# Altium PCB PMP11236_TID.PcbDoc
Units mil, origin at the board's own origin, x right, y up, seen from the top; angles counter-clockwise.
Board outline 1771.65 x 787.4 mil, 2 copper layers (Top Layer, Bottom Layer), stack 62 mil thick; 37 components, 20 nets, 78 pads, 8 vias.
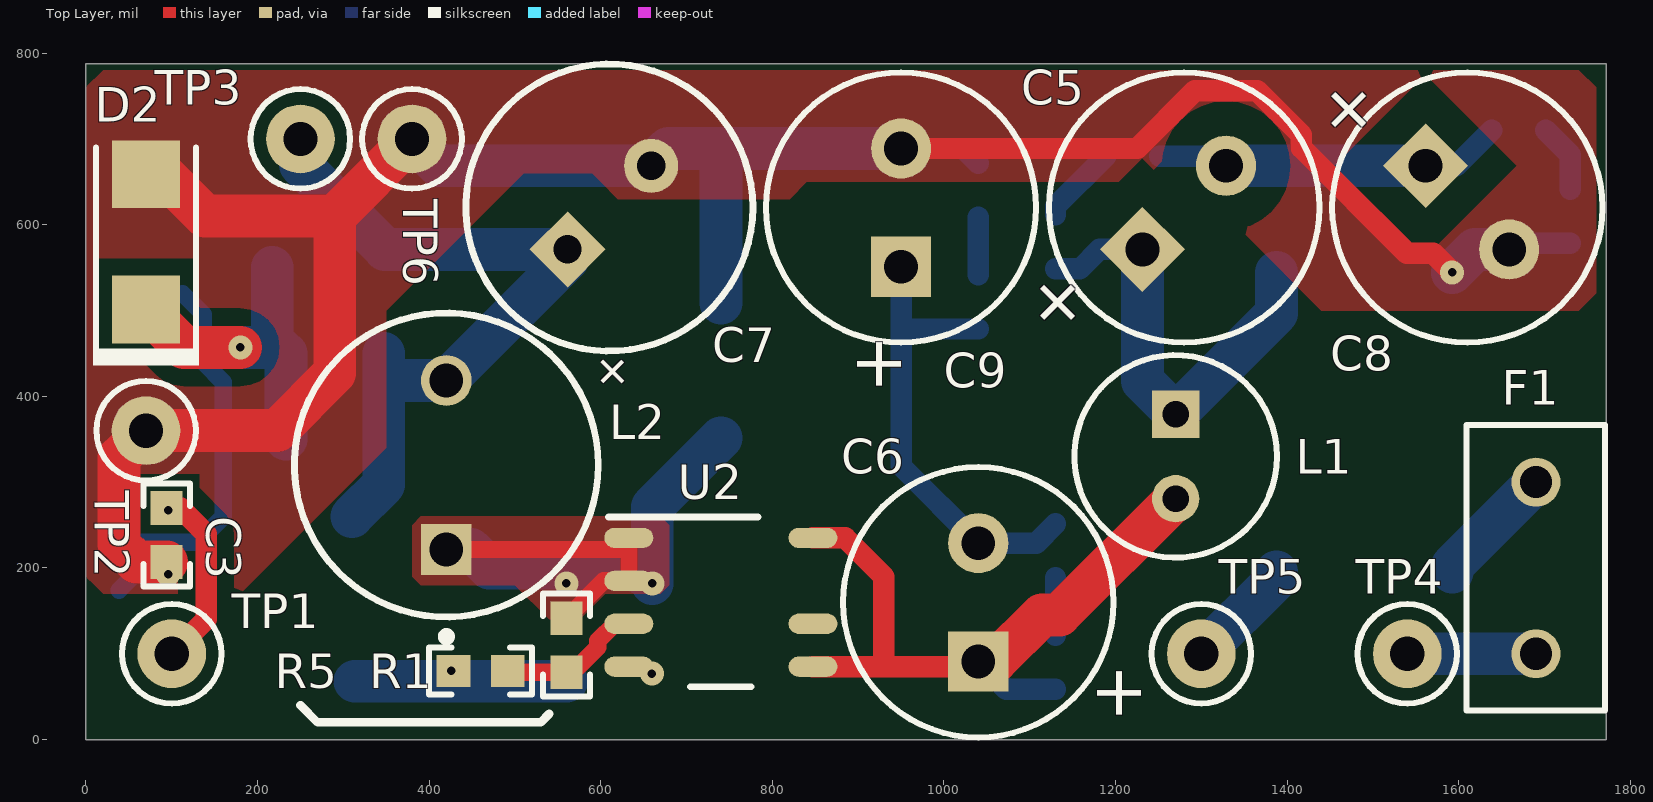
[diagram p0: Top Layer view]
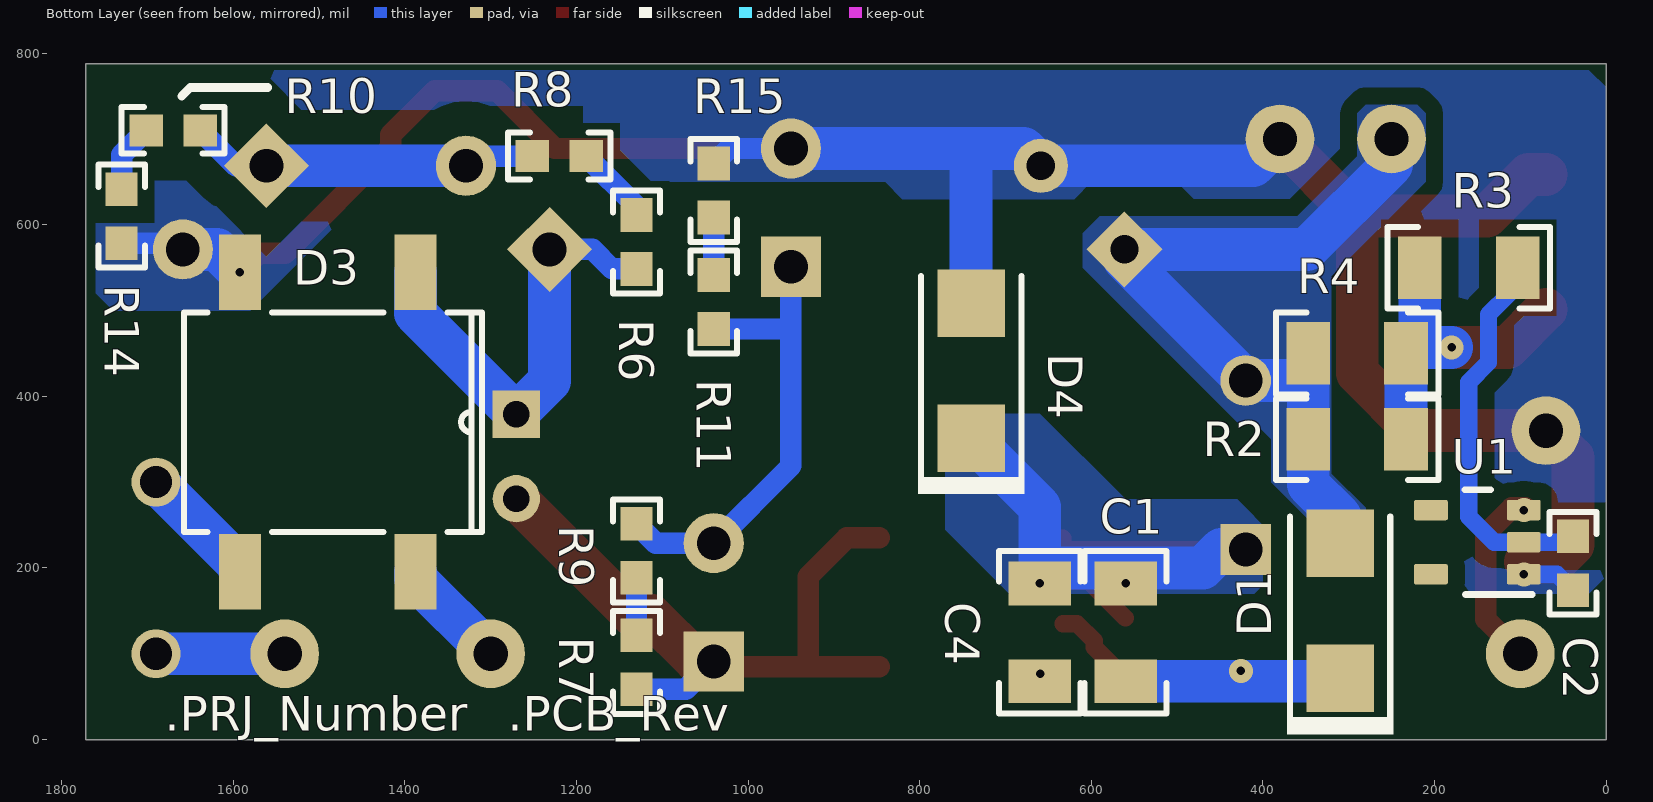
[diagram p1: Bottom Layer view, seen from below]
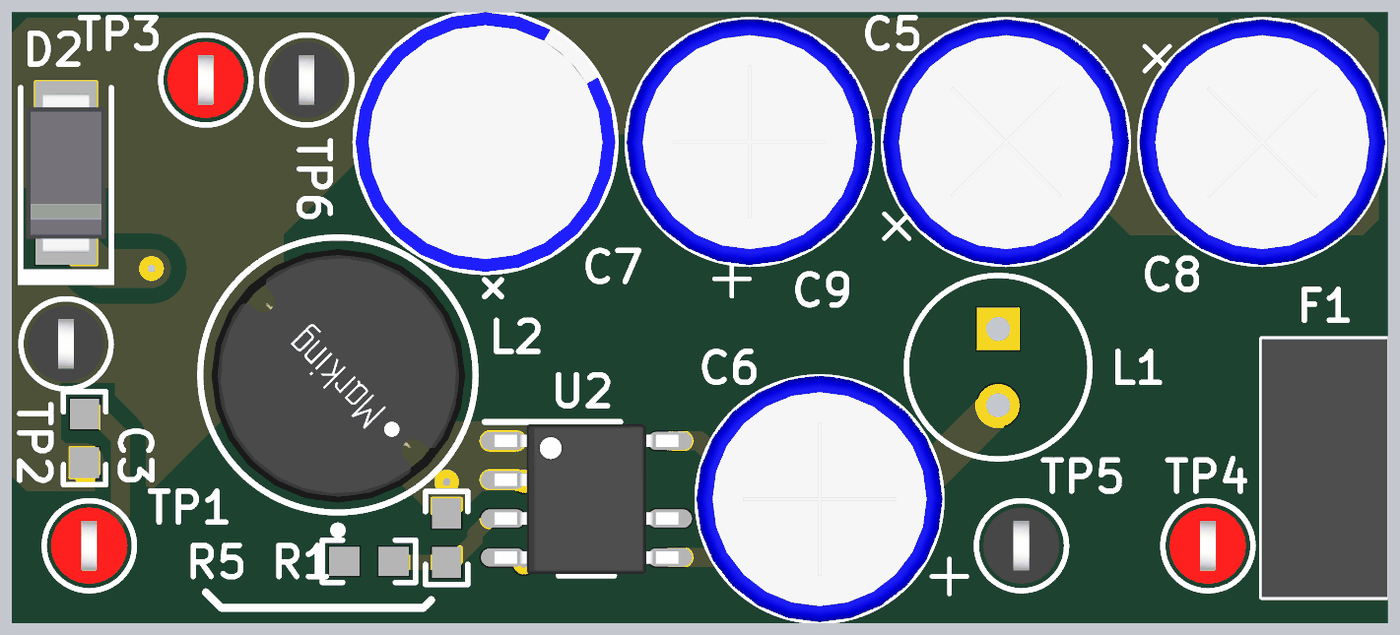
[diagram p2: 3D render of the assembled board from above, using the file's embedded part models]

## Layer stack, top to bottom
Top Solder: solder mask 0.4, Solder Resist, Dk 3.5
Top Layer: signal copper 1.4
Dielectric1: core 59.2, FR-4, Dk 4.8
Bottom Layer: signal copper 1.4
Bottom Solder: solder mask 0.4, Solder Resist, Dk 3.5

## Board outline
0,0 1771.65,0 1771.65,787.4 0,787.4

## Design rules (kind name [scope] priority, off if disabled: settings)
AcuteAngle [All] p1: minimum=4.50000000000000E+0001 checktracksonly=FALSE
AssemblyTestPointUsage [All] p1: valid=2
Clearance Clearance_1 [InNetClass('HV') vs InNet('GND')] p1: gap=40
Clearance Clearance_Keepouts [((IsTrack Or IsArc) And Not InPoly) And IsFree and IsKeepOut vs ((IsTrack Or IsArc) And Not InPoly) And IsFree and IsKeepOut] p2: gap=0
Clearance Clearance_BoardEdge_MountingHoles [OnCopper and InComponentClass('Mounting Holes') vs IsKeepOut] p3: gap=40
Clearance Clearance_BoardEdge_Poly [OnCopper and InPoly vs IsKeepOut] p4: gap=25
Clearance Clearance_BoardEdge [OnCopper and Not InComponentClass('Logo') and not InComponentClass('FiducialMark') and not InRegion(1000,500,4000,800) and Not IsKeepout vs IsKeepOut] p5: gap=75
Clearance Clearance_Poly [InPolygon] p6: gap=20
Clearance [All] p7: gap=7.87
ComponentClearance ComponentClearance_MountingHoles_FiducialMarks [InComponentClass('Mounting Holes') vs InComponentClass('FiducialMark')] p1: gap=20 collisioncheckmode=3 verticalgap=10 showdistances=FALSE
ComponentClearance ComponentClearance_Shunt [InComponentClass('Header') vs InComponentClass('Shunt')] p2: gap=0 collisioncheckmode=3 verticalgap=0 showdistances=FALSE
ComponentClearance ComponentClearance_Logo [InComponentClass('Logo')] p3: gap=5 collisioncheckmode=3 verticalgap=10 showdistances=FALSE
ComponentClearance ComponentClearance_ScrewToNut [(HasFootprint('NY PMS 440 0025 PH')) vs (HasFootprint('Keystone_1902C'))] p4: gap=20 collisioncheckmode=3 verticalgap=100000 showdistances=FALSE
ComponentClearance ComponentClearance_MountingHoles [InComponentClass('Mounting Holes')] p5: gap=20 collisioncheckmode=3 verticalgap=10 showdistances=FALSE
ComponentClearance ComponentClearance_SmallPassives [HasFootprint('0201*') or HasFootprint('0402*') or HasFootprint('0508') or HasFootprint('0603*') or HasFootprint('0612') or HasFootprint('0805*') or HasFootprint('0815*') or HasFootprint('0830*') or HasFootprint('1206*') or HasFootprint('1210*') or HasFootprint('1808*') or HasFootprint('1812*') or HasFootprint('1825*') or HasFootprint('2010*') or HasFootprint('2220*') or HasFootprint('2225*') or HasFootprint('2512*') or HasFootprint('2728*') or HasFootprint('3518*') vs HasFootprint('0201*') or HasFootprint('0402*') or HasFootprint('0508') or HasFootprint('0603*') or HasFootprint('0612') or HasFootprint('0805*') or HasFootprint('0815*') or HasFootprint('0830*') or HasFootprint('1206*') or HasFootprint('1210*') or HasFootprint('1808*') or HasFootprint('1812*') or HasFootprint('1825*') or HasFootprint('2010*') or HasFootprint('2220*') or HasFootprint('2225*') or HasFootprint('2512*') or HasFootprint('2728*') or HasFootprint('3518*')] p6: gap=20 collisioncheckmode=3 verticalgap=20 showdistances=FALSE
ComponentClearance ComponentClearance_THtoSMT [IsThruComponent vs IsSMTComponent] p7: gap=10 collisioncheckmode=3 verticalgap=10 showdistances=FALSE
ComponentClearance ComponentClearance_THtoTH [IsThruComponent vs IsThruComponent] p8: gap=10 collisioncheckmode=3 verticalgap=10 showdistances=FALSE
ComponentClearance [All] p9: gap=10 collisioncheckmode=3 verticalgap=10 showdistances=FALSE
DiffPairsRouting [All] p1: maxlimit=100 minlimit=10 mostfreqgap=10 toplayer_minwidth=15 toplayer_maxwidth=15 toplayer_prefwidth=15 bottomlayer_minwidth=15 bottomlayer_maxwidth=15 bottomlayer_prefwidth=15 maxuncoupledlength=1000
FabricationTestPointUsage TestPointUsage [All] p1: valid=2 allowmultiple=FALSE
FabricationTestpoint Testpoint [All] p1: side=3 testpointundercomponent=TRUE minsize=40 maxsize=100 preferedsize=60 minholesize=0 maxholesize=40 preferedholesize=32 testpointgrid=1 allowsidetop=TRUE allowsidebottom=TRUE usegrid=TRUE gridtolerance=0.01
FanoutControl Fanout_LCC [IsLCC] p1: bgadir=Out bgaviamode=Centered fanoutstyle=Auto fanoutdirection=Alternating viagrid=1 // Fanout_LCC (Default Rule)
FanoutControl Fanout_BGA [IsBGA] p2: bgadir=Out bgaviamode=Centered fanoutstyle=Auto fanoutdirection=Alternating viagrid=1 // Fanout_BGA (Default Rule)
FanoutControl Fanout_Default [All] p4: bgadir=Out bgaviamode=Centered fanoutstyle=Auto fanoutdirection=Alternating viagrid=1 // Fanout_Default (Default Rule)
FanoutControl Fanout_Small [(CompPinCount < 5)] p5: bgadir=Out bgaviamode=Centered fanoutstyle=Auto fanoutdirection=OutThenIn viagrid=1 // Fanout_Small (Default Rule)
Height [All] p1: minheight=0 maxheight=3000 prefheight=500
HoleSize [All] p1: absolutevalues=TRUE maxlimit=251 minlimit=7 maxpercent=80.000 minpercent=20.000
MinimumAnnularRing MinimumAnnularRing_ThermalPadVias [IsVia and InAnyComponent] p1: minimumring=5.91
MinimumAnnularRing [All] p2: minimumring=9
MinimumSolderMaskSliver MinimumSolderMaskSliver_Logo [InComponentClass('Logo') vs InComponentClass('Logo')] p1: minsoldermaskwidth=0.7
MinimumSolderMaskSliver [All] p2: minsoldermaskwidth=2
PlaneConnect [All] p1: planeconnectstyle=Relief reliefexpansion=10 reliefentries=4 reliefconductorwidth=10 reliefairgap=10
PolygonConnect PolygonConnect_7 [All vs IsNamedPolygon('GND') Or  IsNamedPolygon('C7_1') Or  IsNamedPolygon('GND') Or  IsNamedPolygon('C1_2') Or  IsNamedPolygon('C1_2')] p1: connectstyle=Direct reliefconductorwidth=10 reliefentries=4 polygonreliefangle="90 Angle" airgapwidth=10
PolygonConnect PolygonConnect_6 [All vs IsNamedPolygon('GND2') Or  IsNamedPolygon('SGND') Or  IsNamedPolygon('GND1') Or  IsNamedPolygon('C901_1') Or  IsNamedPolygon('SGND') Or  IsNamedPolygon('GND2') Or  IsNamedPolygon('GND1')] p2: connectstyle=Direct reliefconductorwidth=10 reliefentries=4 polygonreliefangle="90 Angle" airgapwidth=10
PolygonConnect PolygonConnect_5 [All vs IsNamedPolygon('GND1') Or  IsNamedPolygon('GND1')] p3: connectstyle=Direct reliefconductorwidth=10 reliefentries=4 polygonreliefangle="90 Angle" airgapwidth=10
PolygonConnect PolygonConnect_4 [All vs IsNamedPolygon('C21_1') Or  IsNamedPolygon('C5_1') Or  IsNamedPolygon('C12_2') Or  IsNamedPolygon('C2_2') Or  IsNamedPolygon('C13_1') Or  IsNamedPolygon('C28_1') Or  IsNamedPolygon('C6_1') Or  IsNamedPolygon('GND') Or  IsNamedPolygon('GND2') Or  IsNamedPolygon('C14_1') Or  IsNamedPolygon('C13_1') Or  IsNamedPolygon('Q1_3') Or  IsNamedPolygon('C14_1') Or  IsNamedPolygon('C5_1') Or  IsNamedPolygon('GND2') Or  IsNamedPolygon('C28_1') Or  IsNamedPolygon('D5_2') Or  IsNamedPolygon('D6_2') Or  IsNamedPolygon('D2_1') Or  IsNamedPolygon('C12_2') Or  IsNamedPolygon('D2_1') Or  IsNamedPolygon('C4_1') Or  IsNamedPolygon('C4_1') Or  IsNamedPolygon('C2_2') Or  IsNamedPolygon('GND') Or  IsNamedPolygon('C33_1') Or  IsNamedPolygon('C9_1')] p4: connectstyle=Direct reliefconductorwidth=10 reliefentries=4 polygonreliefangle="90 Angle" airgapwidth=10
PolygonConnect PolygonConnect_3 [All vs IsNamedPolygon('C28_1') Or  IsNamedPolygon('C12_2') Or  IsNamedPolygon('C28_1') Or  IsNamedPolygon('C9_1') Or  IsNamedPolygon('D5_2') Or  IsNamedPolygon('C12_2') Or  IsNamedPolygon('C2_2') Or  IsNamedPolygon('C14_1') Or  IsNamedPolygon('C4_1') Or  IsNamedPolygon('C14_1') Or  IsNamedPolygon('D6_2') Or  IsNamedPolygon('GND2') Or  IsNamedPolygon('Q1_3') Or  IsNamedPolygon('C5_1') Or  IsNamedPolygon('D2_1') Or  IsNamedPolygon('C4_1') Or  IsNamedPolygon('C13_1') Or  IsNamedPolygon('C5_1') Or  IsNamedPolygon('C13_1') Or  IsNamedPolygon('C33_1') Or  IsNamedPolygon('D2_1') Or  IsNamedPolygon('GND') Or  IsNamedPolygon('GND') Or  IsNamedPolygon('GND2') Or  IsNamedPolygon('C2_2') Or  IsNamedPolygon('C6_1') Or  IsNamedPolygon('C21_1')] p5: connectstyle=Direct reliefconductorwidth=10 reliefentries=4 polygonreliefangle="90 Angle" airgapwidth=10
PolygonConnect PolygonConnect_2 [All vs IsNamedPolygon('C21_1') Or  IsNamedPolygon('C4_1') Or  IsNamedPolygon('D5_2') Or  IsNamedPolygon('C5_1') Or  IsNamedPolygon('C14_1') Or  IsNamedPolygon('C13_1') Or  IsNamedPolygon('C4_1') Or  IsNamedPolygon('C33_1') Or  IsNamedPolygon('C12_2') Or  IsNamedPolygon('D2_1') Or  IsNamedPolygon('C2_2') Or  IsNamedPolygon('C28_1') Or  IsNamedPolygon('C12_2') Or  IsNamedPolygon('D2_1') Or  IsNamedPolygon('C5_1') Or  IsNamedPolygon('Q1_3') Or  IsNamedPolygon('GND') Or  IsNamedPolygon('D6_2') Or  IsNamedPolygon('C6_1') Or  IsNamedPolygon('C2_2') Or  IsNamedPolygon('C14_1') Or  IsNamedPolygon('C28_1') Or  IsNamedPolygon('C13_1') Or  IsNamedPolygon('C9_1') Or  IsNamedPolygon('GND')] p6: connectstyle=Direct reliefconductorwidth=10 reliefentries=4 polygonreliefangle="90 Angle" airgapwidth=10
PolygonConnect PolygonConnect_1 [All vs IsNamedPolygon('C28_1') Or  IsNamedPolygon('D5_2') Or  IsNamedPolygon('C5_1') Or  IsNamedPolygon('C5_1') Or  IsNamedPolygon('D2_1') Or  IsNamedPolygon('C21_1') Or  IsNamedPolygon('C9_1') Or  IsNamedPolygon('C4_1') Or  IsNamedPolygon('C14_1') Or  IsNamedPolygon('C28_1') Or  IsNamedPolygon('C6_1') Or  IsNamedPolygon('C12_2') Or  IsNamedPolygon('C33_1') Or  IsNamedPolygon('C4_1') Or  IsNamedPolygon('C13_1') Or  IsNamedPolygon('C12_2') Or  IsNamedPolygon('D6_2') Or  IsNamedPolygon('C2_2') Or  IsNamedPolygon('C14_1') Or  IsNamedPolygon('D2_1') Or  IsNamedPolygon('C2_2') Or  IsNamedPolygon('C13_1')] p7: connectstyle=Direct reliefconductorwidth=10 reliefentries=4 polygonreliefangle="90 Angle" airgapwidth=10
PolygonConnect [All] p8: connectstyle=Relief reliefconductorwidth=10 reliefentries=4 polygonreliefangle="90 Angle" airgapwidth=10
RoutingVias ThermalPadVias [IsVia and InAnyComponent] p1: holewidth=7.87 width=19.68 viastyle="Through Hole" minholewidth=7.87 minwidth=19.68 maxholewidth=12.99 maxwidth=23.62
RoutingVias [All] p2: holewidth=16 width=34 viastyle="Through Hole" minholewidth=7.87 minwidth=26 maxholewidth=40 maxwidth=65
SilkToBoardRegionClearance [Not ((IsComment or IsDesignator) And (Hide <> 'False')) and not InRegion(1000,500,4000,800)] p1:
SilkToSilkClearance SilkToSilkClearance_Pb-FreeLogo [(HasFootprint('Pb-Free_Overlay_Medium') OR HasFootprint('Pb-Free_Overlay_Small')) vs (HasFootprint('Pb-Free_Overlay_Medium') OR HasFootprint('Pb-Free_Overlay_Small'))] p1: silktosilkclearance=0
SilkToSilkClearance [All] p2: silktosilkclearance=1
SilkToSolderMaskClearance "Silk to Solder Mask Opening" [All] p1: minsilkscreentomaskgap=1 clearancetoexposedcopper=FALSE
SolderMaskExpansion [All] p1: expansion=1.97
UnpouredPolygon [All] p1: allowunpoured=FALSE
Width [All] p1: maxlimit=100 minlimit=6 preferedwidth=10 checkconnectedcopper=TRUE
13 further rules are at their usual default settings.

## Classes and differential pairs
net class HV: NetC1_2 NetC5_1 NetC5_2 NetC6_1 NetC6_2 NetD3_3 NetD3_4 NetF1_2 NetR1_1

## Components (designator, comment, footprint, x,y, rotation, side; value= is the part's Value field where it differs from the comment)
C1 "12065C104JAT2A" 1206 560,125 r90 bottom
C2 "06033C104JAT2A" 0603 38.5,205.49 r270 bottom
C3 "C0603C105K4PACTU" 0603 93.97,238.45 r270 top
C4 "12065C223KAT2A" 1206 660,125 r90 bottom
C5 "400AX6R8M8x11" CAPPRD350W60D800H1100 1280,620 r45 top
C6 "400AX6R8M8x11" CAPPRD350W60D800H1100 1040,160 r90 top
C7 "UPW1V151MPD" HE_800x1150 610,620 r45 top
C8 "400AX6R8M8x11" CAPPRD350W60D800H1100 1610,620 r315 top
C9 "400AX6R8M8x11" CAPPRD350W60D800H1100 950,620 r90 top
D1 "ES1K-TP" SMA 310,150 r90 bottom
D2 "1SMA5927BT3G" SMA 70,580 r90 top
D3 "DF10SA" DF-S 1490,370 r270 bottom
D4 "US1K-13-F" SMA 740,430 r90 bottom
F1 "RST 500" Fuse_RST 1690,200 r270 top
L1 "7447462102" WE-TI_5075 1270,330 r270 top
L2 "744741101" WE-TI_8055 420,320 r90 top
R1 "CRCW0603232KFKEA" 0603 460,80 r180 top
R2 "CRCW12061K50FKEA" 1206 290,350 r180 bottom
R3 "CRCW1206100RFKEA" 1206 160,550 r180 bottom
R4 "CRCW12061K50FKEA" 1206 290,450 r180 bottom
R5 "CRCW060310K0FKEA" 0603 560,110 r270 top
R6 "CRCW06031M00JNEA" 0603 1130,580 r270 bottom
R7 "CRCW06031M00JNEA" 0603 1130,90 r270 bottom
R8 "CRCW06031M00JNEA" 0603 1220,680 r180 bottom
R9 "CRCW06031M00JNEA" 0603 1130,220 r270 bottom
R10 "CRCW06031M00JNEA" 0603 1670,710 r180 bottom
R11 "CRCW06031M00JNEA" 0603 1040,510 r270 bottom
R14 "CRCW06031M00JNEA" 0603 1730,610 r90 bottom
R15 "CRCW06031M00JNEA" 0603 1040,640 r270 bottom
TP1 "5000" Keystone5000 100,100 r0 top
TP2 "5001" Keystone5001 70,360 r0 top
TP3 "5000" Keystone5000 250,700 r0 top
TP4 "5000" Keystone5000 1540,100 r0 top
TP5 "5001" Keystone5001 1300,100 r0 top
TP6 "5001" Keystone5001 380,700 r0 top
U1 "TLV70450DBVT" DBV0005A_N 150,230 r0 bottom
U2 "UCC28880DR" D0007A_N 740,160 r0 top

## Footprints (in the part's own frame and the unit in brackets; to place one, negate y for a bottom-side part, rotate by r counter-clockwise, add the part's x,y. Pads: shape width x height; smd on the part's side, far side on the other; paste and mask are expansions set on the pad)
0603 [mm] "0603 from SM-752 data"
  rect 1x0.95 smd: 1(-0.8,0) 2(0.8,0)
  silkscreen extent -1.52,-0.69 1.52,0.69, body extent -0.87,-0.47 0.87,0.47, height 0.85
1206 [mm] "1206 from SM-752 data"
  rect 1.3x1.85 smd: 1(-1.45,0) 2(1.45,0)
  silkscreen extent -2.4,-1.21 2.4,1.21, body extent -1.7,-0.9 1.7,0.9, height 1.35
CAPPRD350W60D800H1100 [mm] "Capacitor, Alum, 8x11mm"
  rect 1.78x1.78 hole 1: 1(-1.75,0)
  round 1.78 hole 1: 2(1.75,0)
  silkscreen extent -4,-4 4,4, body extent -4.03,-4.03 4.03,4.02, height 11.79
D0007A_N [mm] "SOIC, 7-Leads, Body 4.9x3.9mm, Pitch 1.27mm, IPC Medium Density"
  oval 1.45x0.6 smd: 1(-2.725,1.905) 2(-2.725,0.635) 3(-2.725,-0.635) 4(-2.725,-1.905) 5(2.725,-1.905) 6(2.725,-0.635) 8(2.725,1.905)
  silkscreen extent -3.32,-2.5 1.1,2.52, body extent -3.01,-2.45 3.01,2.45, height 1.75
DBV0005A_N [mm] "SOT23, 5-Leads, Body 2.9x1.6mm, Pitch 0.95mm, Lead Span 2.8mm, IPC Medium Density"
  rrect17% 1x0.6 smd: 1(-1.375,0.95) 2(-1.375,0) 3(-1.375,-0.95) 4(1.375,-0.95) 5(1.375,0.95)
  silkscreen extent -1.63,-1.55 0.38,1.55, body extent -1.42,-1.46 1.42,1.46, height 1.09
DF-S [mil] "Diodes Inc. recommended land pattern per ap02001.pdf rev 30"
  rect 88x49 smd: 1(-174.5,102.36) 2(-174.5,-102.36) 3(174.5,-102.36) 4(174.5,102.36)
  silkscreen extent -128,-168 128,180, body extent -205,-168 205,168, height 108
Fuse_RST [mm] "Bel Fuse RST series May2012D"
  round 1.45 hole 0.95: 1(-2.54,0) 2(2.54,0)
  silkscreen extent -4.23,-2.05 4.23,2.05, body extent -4.22,-2.05 4.23,2.05, height 7.9
HE_800x1150 [mm] "NICHICON"
  rect 1.6x1.6 hole 0.838: 1(-1.75,0)
  round 1.6 hole 0.838: 2(1.75,0)
  silkscreen extent -4.25,-4.25 4.25,4.25, body extent -4.22,-4.24 4.24,4.24, height 11.51
Keystone5000 [mil] "For Keystone 500x miniature loop terminals"
  round 80 hole 40: 1(0,0)
  silkscreen extent -58,-58 58,58, body extent -49,-49 49,49, height 182
Keystone5001 [mil] "For Keystone 500x miniature loop terminals"
  round 80 hole 40: 1(0,0)
  silkscreen extent -58,-58 58,58, body extent -49,-49 49,49, height 182
SMA [mm] "Molded Diode, 2-Leads, Body 4.3x2.6mm, IPC Medium Density, based on OnSemi component dimensions and land pattern"
  rect 2x2 smd: 1(-2,0) 2(2,0)
  silkscreen extent -3.66,-1.57 2.79,1.57, body extent -2.6,-1.3 2.6,1.3, height 2.42
WE-TI_5075 [mm] "Wurth WE-TI 5075"
  rect 1.4x1.4 hole 0.787: 1(-1.25,0)
  round 1.4 hole 0.787: 2(1.25,0)
  silkscreen extent -3,-3 3,3, body extent -3.01,-3.01 3.01,3.01, height 8.5
WE-TI_8055 [mm] "Wurth"
  rect 1.5x1.5 hole 1: 1(-2.5,0)
  round 1.5 hole 1: 2(2.5,0)
  silkscreen extent -5.21,-4.5 4.5,4.5, body extent -5.89,-5.88 5.81,5.83, height 5.51

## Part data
C1: "CAP, CERM, 0.1uF, 50V, +/-5%, X7R, 1206"
C2: "CAP, CERM, 0.1 µF, 25 V, +/- 5%, X7R, 0603"
C3: "CAP, CERM, 1 µF, 16 V, +/- 10%, X5R, 0603"
C4: "CAP, CERM, 0.022uF, 50V, +/-10%, X7R, 1206"
C5 C6 C8 C9: "CAP, AL, 6.8 µF, 400 V, +/- 20%, TH"
C7: library part UHE1H101MPD, "CAP ALUM 150UF 35V 20% RADIAL"
D1: library part ES1D-13-F, "DIODE GEN PURP 800V 1A DO214AC"
D2: "Diode, Zener, 12 V, 1.5 W, SMA"
D3: "Diode, Switching-Bridge, 1000 V, 1 A, DF-S"
D4: "Diode, Fast Rectifier, 800 V, 1 A, SMA"
F1: "Fuse, 0.5 A, 250 V, TH"
L1: "Inductor, Unshielded Drum Core, Ferrite, 1 mH, 0.25 A, 4.38 ohm, TH"
L2: "Inductor, Wirewound, Ferrite, 100 µH, 1.1 A, 0.39 ohm, TH"
R1: "RES, 232 k, 1%, 0.1 W, 0603"
R2 R4: "RES, 1.50 k, 1%, 0.25 W, 1206"
R3: "RES, 100, 1%, 0.25 W, 1206"
R5: "RES, 10.0k ohm, 1%, 0.1W, 0603"
R6 R7 R8 R9 R10 R11 R14 R15: "RES, 1.0 M, 5%, 0.1 W, 0603"
TP1 TP3 TP4: "Test Point, Miniature, Red, TH"
TP2 TP5 TP6: "Test Point, Miniature, Black, TH"
U1: "Single Output LDO, 150 mA, Fixed 5 V Output, 2.5 to 24 V Input, with Ultra-Low IQ, 5-pin SOT-23 (DBV), -40 to 125 degC, Green (RoHS & no Sb/Br)"
U2: "700-V Lowest Quiescent Current Off-Line Switcher, D0007A"

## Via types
v1: diameter 28, hole 10, Top Layer to Bottom Layer, 8 vias

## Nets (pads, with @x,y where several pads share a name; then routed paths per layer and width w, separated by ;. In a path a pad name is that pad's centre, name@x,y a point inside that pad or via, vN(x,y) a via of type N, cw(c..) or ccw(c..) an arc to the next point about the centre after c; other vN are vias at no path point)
GND: C2.2 C3.2 C7.2 C8.2 C9.2 D2.2 D3.2 D4.2 R14.1 R15.1 TP2.1 TP6.1 U1.1 | length 2829.9
  Top Layer w25: C9.2 1225.1,688.9 1292.46,756.26 1364.98,756.26 1416.26,704.98 1416.26,689.94 1539.54,566.66 1570.2,566.66 v1(1592.36,544.5)
  Top Layer w50: D2.2 90.16,658.74 138.9,610 290,610 ; C3.2 58.69,206.95 38.5,227.14 38.5,328.5 TP2.1 222.76,360 290,427.24 290,610 ; TP6.1 290,610
  Bottom Layer w20: C2.2 57.11,192.6 v1(95.87,192.6)
  Bottom Layer w25: C9.2 1022.6,688.9 R15.1 ; C8.2@1665.94,578.5 R14.1
  Bottom Layer w50: TP6.1 411.28,668.72 C7.2 678.9,688.9 C9.2 ; D4.2 740,668.9 ; v1(1592.36,544.5) 1619.14,571.28 C8.2
NetC1_1: C1.1 D1.1 R1.2 | length 246.7
  Bottom Layer w50: D1.1@313.35,67.91 C1.1
  other v1: 425.57,80
NetC1_2: C1.2 C4.2 D4.1 L2.1 R5.1 U2.1 U2.2 | length 803.1
  Top Layer w20: L2.1 631.14,221.57 ; R5.1 603.5,185 U2.2 U2.1
  Bottom Layer w25: C4.2@642.09,182.09 v1(660,182.09)
  Bottom Layer w50: L2.1 448.43,221.57 470,200 C4.2@642.09,200 ; v1(660,182.09) 660,271.26 D4.1
  other v1: 560,182.09
NetC2_1: C2.1 R3.2 U1.2 | length 406.8
  Bottom Layer w20: C2.1@45.48,230 U1.2 130.32,230 160,259.68 160,416.45 137.13,439.33 137.13,495.32 R3.2@112.44,520
NetC3_1: C3.1 TP1.1 U1.3 | length 214.8
  Top Layer w25: C3.1 109.74,269.94 140,239.68 140,140 TP1.1
  other v1: 95.87,267.4
NetC4_1: C4.1 U2.4
  other v1: 659.49,76.93
NetC5_1: C5.1 D3.1 L1.1 R6.2 | length 532.8
  Bottom Layer w25: R6.2 1158.5,548.5 1181.28,571.28 C5.1
  Bottom Layer w50: C5.1 1231.28,417.93 L1.1 1387.64,496.85 D3.1
NetC5_2: C5.2 C8.1 R8.1 R10.2 | length 392.8
  Bottom Layer w25: R8.1 C5.2@1317.44,680 ; C8.1 1597.22,668.72 R10.2
  Bottom Layer w50: C5.2 C8.1
NetC6_1: C6.1 L1.2 R7.2 U2.5 U2.8 | length 805
  Top Layer w25: U2.5 930,85 ; U2.8 885,235 930,190 930,85 ; C6.1@1033.9,85 930,85
  Top Layer w50: C6.1 1060,91.1 1114.29,145.39 1134.61,145.39 L1.2
  Bottom Layer w25: C6.1 1072.6,58.5 R7.2
NetC6_2: C6.2 C9.1 R9.1 R11.2 | length 540.3
  Bottom Layer w25: C9.1 950,318.9 C6.2 1107.4,228.9 R9.1 ; 958.5,478.5 R11.2
NetC7_1: C7.1 D1.2 L2.2 R2.1 R4.1 TP3.1 | length 825.8
  Bottom Layer w50: TP3.1@250,670 348.72,571.28 C7.1 561.28,559.71 L2.2 R4.1@363.15,418.43 ; D1.2@310,260 347.09,297.09 R2.1 R4.1
NetD2_1: D2.1 R2.2 R3.1 R4.2 | length 358.3
  Top Layer w50: D2.1 114.17,457.09 v1(180,457.09)
  Bottom Layer w50: v1(180,457.09) R4.2@225.83,457.09 ; R4.2@217.09,465.83 R3.1 ; R2.2 R4.2
NetD3_3: D3.3 F1.1 | length 144.9
  Bottom Layer w50: D3.3 1592.36,202.36 F1.1
NetD3_4: D3.4 TP5.1 | length 131.8
  Bottom Layer w50: TP5.1 1387.64,187.64 D3.4
NetF1_2: F1.2 TP4.1 | length 150
  Bottom Layer w50: TP4.1 F1.2
NetR1_1: R1.1 R5.2 U2.3 | length 167.5
  Top Layer w20: R1.1@492.99,78.5 R5.2 567.51,78.5 596.57,107.57 596.57,115.08 616.5,135 U2.3
NetR6_1: R6.1 R8.2 | length 92.7
  Bottom Layer w25: R6.1 1130,621.5 R8.2
NetR7_1: R7.1 R9.2 | length 67
  Bottom Layer w25: R7.1 R9.2
NetR10_1: R10.1 R14.2 | length 80.3
  Bottom Layer w25: R10.1 1730,681.5 R14.2
NetR11_1: R11.1 R15.2 | length 67
  Bottom Layer w25: R11.1 R15.2
pads on no net: U1.4 U1.5 U2.6

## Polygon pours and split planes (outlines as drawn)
GND on Top Layer "GND" (solid, remove dead copper, pour order 14): 20,170 10,180 0,190 0,200 0,760 20,780 40,780 1740,780 1760,760 1760,740 1760,520 1740,500 1720,500 1440,500 1260,680 1230,650 1120,650 840,650 820,630 740,630 620,630 600,650 590,660 570,660 510,660 390,540 350,500 350,480 350,340 180,170
NetC1_2 on Top Layer "C1_2" (solid, remove dead copper, pour order 10): 390,260 380,250 380,210 380,190 390,180 420,180 500,180 540,140 560,140 575.43,140 595.43,160 605.43,170 606.26,170 670,170 680,180 680,230 680,250 670,260
GND on Bottom Layer "GND" (solid, remove dead copper, pour order 13): 20,170 10,180 0,190 0,200 0,760 20,780 40,780 1740,780 1760,760 1760,740 1760,520 1740,500 1720,500 1580,500 1370,710 1360,720 1320,720 1300,720 1260,680 1230,650 1120,650 840,650 820,630 740,630 620,630 600,650 590,660 570,660 510,660 390,540 350,500 350,480 350,340 180,170
NetC7_1 on Bottom Layer "C7_1" (solid, remove dead copper, pour order 12): 220,740 210,730 210,700 210,650 270,590 320,540 320,485.43 320,310 280,270 280,260 280,240 280,210 300,210 380,290 390,300 390,350 410,370 430,370 560,500 610,550 610,580 610,590 590,610 540,610 360,610 310,660 290,680 290,730 280,740
NetC1_2 on Bottom Layer "C1_2" (solid, remove dead copper, pour order 11): 770,380 770,280 770,244.57 695.43,170 630,170 410,170 400,180 400,200 400,250 420,270 430,280 520,280 560,280 660,380

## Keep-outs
Keep-Out Layer:
  text ".Layer_Name" at 577,-858.49 h60

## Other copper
Top Layer:
  text ".Layer_Name" at 577,-858.49 h60
Bottom Layer:
  text ".Layer_Name" at 577,-858.49 h60

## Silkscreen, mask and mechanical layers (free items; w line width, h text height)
Top Overlay:
  lines w10: 250,40 270,20 530,20 540,30
  text ".Layer_Name" at 577,-858.49 h60
Bottom Overlay:
  lines w10: 1560,760 1650,760 1660,750
  text ".PCB_Rev" at 1280,10 h40
  text ".PRJ_Number" at 1680,10 h40
  text ".Layer_Name" at 577,-858.49 h60
Top Paste:
  text ".Layer_Name" at 577,-858.49 h60
Bottom Paste:
  text ".Layer_Name" at 577,-858.49 h60
Top Solder:
  text ".Layer_Name" at 577,-858.49 h60
  text ".Layer_Name" at 577,-858.49 h60
Bottom Solder:
  text ".Layer_Name" at 577,-858.49 h60
Drill Guide:
  text ".Layer_Name" at 577,-858.49 h60
M1 Board Outline:
  the board outline again, w7.01
  text ".Layer_Name" at 577,-858.49 h60
M2 Board Dimensions:
  rectangle: 0,-275 125,-150
  rectangle: 125,-400 500,-275
  lines w7: 0,-275 1000,-275 ; 125,-400 125,-150 ; 250,-400 250,-150 ; 500,-400 500,-150 ; 750,-400 750,-150 ; 0,-400 1000,-400 1000,-150 0,-150 0,-400
  text ".Layer_Name" at 577,-858.49 h60
M3 3D STEP Top:
  text ".Layer_Name" at 577,-858.49 h60
M4 3D STEP Bottom:
  text ".Layer_Name" at 577,-858.49 h60
M5 Assembly Top:
  lines w10: -292,-930.17 6308,-930.17 ; -292,-726.83 6310,-726.83 ; -292,-523.5 -292,-1133.5 3713,-1133.5 6310,-1133.5 6310,-523.5 -291.5,-523.5 -291.5,-1133.5 1284,-1133.5 ; 2173,-1133.5 2173,-523.5 ; 3440,-726.83 3440,-523.5 ; 4280,-726.83 4280,-523.5 ; 4902,-1140 4902,-937.17
  text "COMPONENTS MARKED 'DNP' SHOULD NOT BE POPULATED." at 1153.5,-318.5 h60
  text "ASSEMBLY VARIANT:" at 1153,-434 h60
  text ".VariantName" at 2189,-434 h60
  text "PCB VIEWED FROM TOP SIDE" at -228.5,-655.67 h60
  text "BOARD #:" at 2248,-655.67 h60
  text ".PRJ_Number" at 2793.5,-655.67 h60
  text "REV:" at 3638,-655.67 h60
  text ".PCB_Rev" at 3929.5,-655.67 h60
  text "SVN REV:" at 4476,-655.67 h60
  text ".VersionControl_RevNumber" at 4982,-655.67 h60
  text "TID #:" at 2248,-859 h60
  text ".TID" at 2793.5,-859 h60
  text "PLOT NAME =" at -228.5,-1064.34 h60
  text ".plot_File_Name" at 577,-1064.34 h60
  text "GENERATED    :" at 2250,-1064.34 h60
  text ".Print_Date" at 3119.5,-1064.34 h60
  text ".Print_Time" at 3848.5,-1064.34 h60
  text "TEXAS INSTRUMENTS" at 5113,-1064.34 h60
M6 Assembly Bottom:
  lines w10: -292.5,-727.33 6309.5,-727.33 ; -290.5,-930.67 6309.5,-930.67 ; 1115.5,-1140.5 1115.5,-937.67 ; 1737.5,-727.33 1737.5,-524 ; 2577.5,-727.33 2577.5,-524 ; 3844.5,-1134 3844.5,-524 ; 4733.5,-1134 6309,-1134 6309,-524 -292.5,-524 -292.5,-1134 2304.5,-1134 6309.5,-1134 6309.5,-524
  text "COMPONENTS MARKED 'DNP' SHOULD NOT BE POPULATED." at 6102,-318 h60
  text ".VariantName" at 5058,-434 h60
  text "ASSEMBLY VARIANT:" at 6097,-434 h60
  text ".VersionControl_RevNumber" at 1035.5,-656.17 h60
  text "SVN REV:" at 1541.5,-656.17 h60
  text ".PCB_Rev" at 2088,-656.17 h60
  text "REV:" at 2379.5,-656.17 h60
  text ".PRJ_Number" at 3224,-656.17 h60
  text "BOARD #:" at 3769.5,-656.17 h60
  text "PCB VIEWED FROM BOTTOM SIDE" at 6246,-656.17 h60
  text ".TID" at 3224,-859.5 h60
  text "TID #:" at 3769.5,-859.5 h60
  text "TEXAS INSTRUMENTS" at 904.5,-1064.84 h60
  text ".Print_Time" at 2169,-1064.84 h60
  text ".Print_Date" at 2898,-1064.84 h60
  text "GENERATED    :" at 3767.5,-1064.84 h60
  text ".plot_File_Name" at 5440.5,-1064.84 h60
  text "PLOT NAME =" at 6246,-1064.84 h60
M9 Title Sheet:
  drawing of 57 lines, arcs and shapes, not listed
  text "1" at 739.84,8036.5 h70
  text "2" at 3235.5,8036.5 h70
  text "3" at 5724.84,8036.5 h70
  text "4" at 8231.51,8036.5 h70
  text "5" at 10730.5,8036.5 h70
  text "6" at 13235.5,8036.5 h70
  text "A" at -416.5,6893.5 h70
  text "A" at 14383.5,6893.5 h70
  text "B" at -416.5,4513.5 h70
  text "B" at 14383.5,4513.5 h70
  text "C" at -416.5,2138.5 h70
  text "C" at 14383.5,2138.5 h70
  text "PROJECT TITLE:" at 11343.5,277.5 h45
  text ".PRJ_Title" at 11393.5,144.17 h70
  text "DESIGNED FOR:" at 11343.5,-23.5 h45
  text ".PRJ_Customer" at 11393.5,-163.5 h70
  text "D" at -416.5,-231.5 h70
  text "D" at 14383.5,-231.5 h70
  text "FILE NAME:" at 11343.5,-323.5 h45
  text ".PCB_File_Name_No_Path" at 11393.5,-443.5 h70
  text "Texas Instruments (TI) and/or its licensors do not warrant the accuracy or completeness of this specification" at 6374,-605.34 h45
  text "ENGINEER:" at 11343.5,-613.5 h45
  text "LAYOUT BY:" at 12848.5,-613.5 h45
  text "or any information contained therein. TI and/or its licensors do not warrant that this design will meet" at 6329.01,-718 h45
  text ".PRJ_Engineer" at 11393.5,-768.49 h70
  text ".PCB_Layout" at 12899,-768.49 h70
  text "the specifications, will be suitable for your application or fit for any particular purpose, or will operate in" at 6329.01,-830.67 h45
  text ".Layer_Name" at 577,-858.49 h60
  text "ALTIUM DESIGNER VERSION:" at 12848.5,-923.5 h45
  text "an implementation. TI and/or its licensors do not warrant that the design is production worthy. You should" at 6329.01,-943.33 h45
  text "completely validate and test your design implementation to confirm the system functionality for your application." at 6374,-1056 h45
  text ".print_Scale" at 11393.5,-1056.83 h70
  text ".Application_BuildNumber" at 12899,-1056.83 h70
  text "1" at 739.84,-1263.5 h70
  text "2" at 3235.5,-1263.5 h70
  text "3" at 5724.84,-1263.5 h70
  text "4" at 8231.51,-1263.5 h70
  text "5" at 10730.5,-1263.5 h70
  text "6" at 13235.5,-1263.5 h70
M10 Fab Notes:
  drawing of 185 lines, arcs and shapes, not listed
  text "DESIGN INFORMATION" at 12381.02,5910 h60
  text "MIN. TRACK WIDTH:" at 11736.46,5730 h60
  text "10" at 12832.7,5730 h60
  text "MIL" at 12987.46,5730 h60
  text "MIN. CLEARANCE:" at 11736.46,5598 h60
  text "0.2" at 12772.7,5598 h60
  text "mm" at 12987.46,5598 h60
  text "MIN. VIA PAD SIZE:" at 11736.46,5466 h60
  text "10" at 12802.71,5466 h60
  text "MIL" at 12987.46,5466 h60
  text "0.05mm (2MIL)" at 12431.46,5324.29 h60
  text "MINIMUM ANNULAR RING" at 11407.23,5320 h60
  text "EXTERNAL" at 13139.46,5320 h60
  text "PER" at 11607.23,5202 h60
  text "IPC-D-275 CLASS 2 LEVEL C" at 11827.23,5202 h60
  text "MIL, HOLES" at 13315.46,5089.71 h60
  text "+/-" at 12923,5089 h60
  text "+/-" at 13777,5089 h60
  text "REGISTRATION TOLERANCES:" at 11407.23,5084 h60
  text "METAL" at 12607,5084 h60
  text "5" at 13183.2,5084 h60
  text "3" at 14016.2,5084 h60
  text "MIL" at 14132.46,5084 h60
  text "MATERIAL:" at 11332.46,4874.54 h60
  text "FR-4 High Tg" at 12318.9,4734.21 h60
  text "FR-408" at 11753.46,4725.64 h60
  text "X" at 12165.46,4725.64 h60
  text "OTHER" at 13241.46,4725.64 h60
  text "62 MIL (1.6mm) +/-10%" at 12073.56,4562.92 h60
  text "THICKNESS:" at 11407.23,4558.64 h60
  text "X" at 11945.4,4558.64 h60
  text "OTHER" at 13358.46,4558.64 h60
  text "TOLERANCE:" at 11407.23,4400.64 h60
  text "X" at 12246.53,4400.64 h60
  text "ANSI IPC-6012 TYPE 3 CLASS 2" at 12433.48,4400.64 h60
  text "OTHER +/-" at 12433.46,4244.64 h60
  text "BOW & TWIST:" at 11407.23,4087.64 h60
  text "X" at 12246.53,4087.64 h60
  text "ANSI IPC-6012 TYPE 3 CLASS 2" at 12433.48,4087.64 h60
  text "OTHER +/-" at 12433.46,3929.13 h60
  text "DRILLING:" at 11332.46,3790.64 h60
  text "REFERENCE:" at 11407.23,3673.64 h60
  text "X" at 12055.46,3673.64 h60
  text "AS SHOWN" at 12242.46,3673.64 h60
  text "X" at 12956.46,3673.64 h60
  text "NC_DRILL FILES" at 13093.46,3673.64 h60
  text "PTH MIN COPPER THICKNESS:" at 11407.23,3515.64 h60
  text "X" at 12757.46,3515.64 h60
  text "1MIL" at 12894.46,3515.64 h60
  text "OTHER" at 13391.46,3515.64 h60
  text "BOARD FINISH:" at 11332.46,3356.64 h60
  text "SILKSCREEN:" at 11487.68,3238.64 h60
  text "X" at 12436.46,3238.64 h60
  text "TOP" at 12562.46,3238.64 h60
  text "X" at 12946.46,3238.64 h60
  text "BOTTOM" at 13073.46,3238.64 h60
  text "SILKSCREEN COLOR:" at 11487.68,3071.64 h60
  text "X" at 12435.42,3071.64 h60
  text "WHITE" at 12562.46,3071.64 h60
  text "OTHER" at 13073.46,3071.64 h60
  text "SOLDER RESIST COLOR:" at 11487.68,2901.64 h60
  text "X" at 12055.42,2742.44 h60
  text "GREEN" at 12182.46,2742.44 h60
  text "BLUE" at 12773.46,2742.44 h60
  text "OTHER" at 13311.46,2742.44 h60
  text "IMMERSION GOLD (ENIG)" at 12393.46,2553.92 h60
  text "ENEPIG" at 13731,2550.64 h60
  text "SURFACE FINISH:" at 11332.46,2549.64 h60
  text "IMM. TIN/SILVER OR EQUIV" at 11662,2392.64 h60
  text "OTHER" at 13093.46,2392.64 h60
  text "X" at 11500,2390 h60
  text "ARRAY/PANEL:" at 11332.46,2213.64 h60
  text "CUT AND TRIM PER MECH LAYER 1" at 12393.46,2209.35 h60
  text "N.C. ROUTE" at 12393.46,2057.64 h60
  text "X" at 13072.46,2057.64 h60
  text "V. SCORE" at 13259.46,2057.64 h60
  text "CERTIFICATION:" at 11332.46,1920.64 h60
  text "MATERIALS AND WORKMANSHIP FOR ALL PCBS" at 12057.46,1920.64 h60
  text "TO MEET OR EXCEED THE REQUIREMENTS OF:" at 12057.46,1822.64 h60
  text "X" at 11683.96,1686.13 h60
  text "ANSI IPC-A-600F CLASS ->" at 11822.96,1686.13 h60
  text "X" at 13462.02,1686.13 h60
  text "2" at 13580.96,1686.14 h60
  text "1" at 13265.96,1684.64 h60
  text "3" at 13934.96,1684.64 h60
  text "X" at 11686.02,1526.64 h60
  text "UL 94V-0" at 11822.96,1526.64 h60
  text "X" at 12498.02,1526.64 h60
  text "RoHS" at 12634.96,1526.64 h60
  text "OTHER" at 13279.36,1526.64 h60
  text "PER ORDER" at 13676.42,1526.64 h60
  text "ADDITIONAL REQUIREMENTS:" at 11332.46,1385.64 h60
  text "MICROSECTION:" at 11407.23,1270.64 h60
  text "YES" at 12312.96,1270.64 h60
  text "REQUIRED" at 13174.46,1114.49 h60
  text "BARE BOARD ELEC. TEST:" at 11407.23,1111.64 h60
  text "NONE" at 12712.96,1111.64 h60
  text "PER ORDER" at 13766.46,1111.64 h60
  text "X" at 12590,1110 h60
  text "MANUFACTURER'S UL:" at 11407.23,954.64 h60
  text "RAIL" at 12572.96,950.35 h60
  text "METAL" at 13064.77,950.35 h60
  text "X" at 13440,950 h60
  text "SILK" at 13576.46,950.35 h60
  text ".Layer_Name" at 577,-858.49 h60
M11 Gerber Information:
  lines w10: -292,-930.17 6308,-930.17 ; -292,-726.83 6310,-726.83 ; -292,-523.5 -292,-1133.5 3713,-1133.5 6310,-1133.5 6310,-523.5 -291.5,-523.5 -291.5,-1133.5 1284,-1133.5 ; 2173,-1133.5 2173,-523.5 ; 3440,-726.83 3440,-523.5 ; 4280,-726.83 4280,-523.5 ; 4902,-1140 4902,-937.17
  text "ALL ARTWORK VIEWED FROM TOP SIDE" at -228.5,-655.67 h60
  text "BOARD #:" at 2248,-655.67 h60
  text ".PRJ_Number" at 2793.5,-655.67 h60
  text "REV:" at 3638,-655.67 h60
  text ".PCB_Rev" at 3929.5,-655.67 h60
  text "SVN REV:" at 4476,-655.67 h60
  text ".VersionControl_RevNumber" at 4982,-655.67 h60
  text "LAYER NAME =" at -228.5,-858.49 h60
  text "TID #:" at 2248,-859 h60
  text ".TID" at 2793.5,-859 h60
  text "PLOT NAME =" at -228.5,-1064.34 h60
  text ".plot_File_Name" at 577,-1064.34 h60
  text "GENERATED    :" at 2250,-1064.34 h60
  text ".Print_Date" at 3119.5,-1064.34 h60
  text ".Print_Time" at 3848.5,-1064.34 h60
  text "TEXAS INSTRUMENTS" at 5113,-1064.34 h60
M12 Stackup:
  drawing of 191 lines, arcs and shapes, not listed
  text "Layer" at 9790.58,7830 h60
  text "Name" at 10200.49,7830 h60
  text "Material" at 11130.23,7830 h60
  text "Thickness" at 11990,7830 h60
  text "Constant" at 12639.84,7830 h60
  text "Board Layer Stack" at 13209.7,7830 h60
  text "1" at 9790.58,7710 h60
  text "Top Overlay" at 10200.49,7710 h60
  text "2" at 9790.58,7590 h60
  text "Top Solder" at 10200.49,7590 h60
  text "Solder Resist" at 11130.23,7590 h60
  text "0.40mil" at 11990,7590 h60
  text "3.5" at 12639.84,7590 h60
  text "3" at 9790.58,7470 h60
  text "Top Layer" at 10200.49,7470 h60
  text "Copper" at 11130.23,7470 h60
  text "1.40mil" at 11990,7470 h60
  text "4" at 9790.58,7350 h60
  text "Dielectric1" at 10200.49,7350 h60
  text "FR-4" at 11130.23,7350 h60
  text "59.20mil" at 11990,7350 h60
  text "4.8" at 12639.84,7350 h60
  text "5" at 9790.58,7230 h60
  text "Bottom Layer" at 10200.49,7230 h60
  text "Copper" at 11130.23,7230 h60
  text "1.40mil" at 11990,7230 h60
  text "6" at 9790.58,7110 h60
  text "Bottom Solder" at 10200.49,7110 h60
  text "Solder Resist" at 11130.23,7110 h60
  text "0.40mil" at 11990,7110 h60
  text "3.5" at 12639.84,7110 h60
  text "7" at 9790.58,6990 h60
  text "Bottom Overlay" at 10200.49,6990 h60
  text ".Layer_Name" at 577,-858.49 h60
M13 Component Bodies Top:
  text ".Layer_Name" at 577,-858.49 h60
M14 Component Bodies Bottom:
  text ".Layer_Name" at 577,-858.49 h60
M15 Courtyards Top:
  text ".Layer_Name" at 577,-858.49 h60
M16 Courtyards Bottom:
  text ".Layer_Name" at 577,-858.49 h60
Drill Drawing:
  circle w1: c5572.8,2921.91 r24.91
  lines w1: 5547.89,2461.08 5560.35,2461.08 5560.35,2448.63 5585.26,2448.63 5585.26,2461.08 5597.71,2461.08 5597.71,2485.99 5585.26,2485.99 5585.26,2498.45 5560.35,2498.45 5560.35,2485.99 5547.89,2485.99 5547.89,2461.08 ; 5547.89,2598.09 5572.8,2610.54 5597.71,2598.09 5585.26,2623 5597.71,2647.9 5572.8,2635.45 5547.89,2647.9 5560.35,2623 5547.89,2598.09 ; 5547.89,2760 5560.35,2760 5572.8,2747.54 5585.26,2760 5597.71,2760 5585.26,2772.45 5597.71,2784.91 5585.26,2784.91 5572.8,2797.36 5560.35,2784.91 5547.89,2784.91 5560.35,2772.45 5547.89,2760 ; 5547.89,3046.46 5597.71,3046.46 5597.71,3096.28 5547.89,3096.28 5547.89,3046.46 ; 5547.89,3195.92 5597.71,3195.92 5597.71,3245.74 5547.89,3245.74 5547.89,3195.92 ; 5557.85,3056.43 5587.75,3056.43 5587.75,3086.32 5557.85,3086.32 5557.85,3056.43
  lines w12: 5480,2403.79 7599.4,2403.79 ; 5480,3300.54 7599.4,3300.54 ; 5850.67,2254.33 5850.67,3450 ; 6207.78,2254.33 6207.78,3450 ; 6869.79,2254.33 6869.79,3450 ; 7154.14,2254.33 7154.14,3450 ; 5480,2254.33 7599.4,2254.33 7599.4,3450 5480,3450 5480,2254.33
  text "Symbol" at 5569.68,3345.38 h72
  text "Quantity" at 5895.51,3345.38 h72
  text "Finished Hole Size" at 6252.62,3345.38 h72
  text "Plated" at 6914.62,3345.38 h72
  text "Hole Type" at 7198.98,3345.38 h72
  text "8" at 5895.51,3195.92 h60
  text "10.00mil (0.254mm)" at 6252.62,3195.92 h60
  text "PTH" at 6914.62,3195.92 h60
  text "Round" at 7198.98,3195.92 h60
  text "2" at 5895.51,3046.46 h60
  text "31.00mil (0.787mm)" at 6252.62,3046.46 h60
  text "PTH" at 6914.62,3046.46 h60
  text "Round" at 7198.98,3046.46 h60
  text "2" at 5895.51,2897 h60
  text "33.00mil (0.838mm)" at 6252.62,2897 h60
  text "PTH" at 6914.62,2897 h60
  text "Round" at 7198.98,2897 h60
  text "2" at 5895.51,2747.54 h60
  text "37.40mil (0.950mm)" at 6252.62,2747.54 h60
  text "PTH" at 6914.62,2747.54 h60
  text "Round" at 7198.98,2747.54 h60
  text "10" at 5895.51,2598.09 h60
  text "39.37mil (1.000mm)" at 6252.62,2598.09 h60
  text "PTH" at 6914.62,2598.09 h60
  text "Round" at 7198.98,2598.09 h60
  text "6" at 5895.51,2448.63 h60
  text "40.00mil (1.016mm)" at 6252.62,2448.63 h60
  text "PTH" at 6914.62,2448.63 h60
  text "Round" at 7198.98,2448.63 h60
  text "30 Total" at 5895.51,2299.17 h60
  text ".Layer_Name" at 577,-858.49 h60

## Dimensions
0,-400 to 1000,-400 on M2 Board Dimensions
0,0 to 0,787.4 on M2 Board Dimensions
0,0 to 1771.65,0 on M2 Board Dimensions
